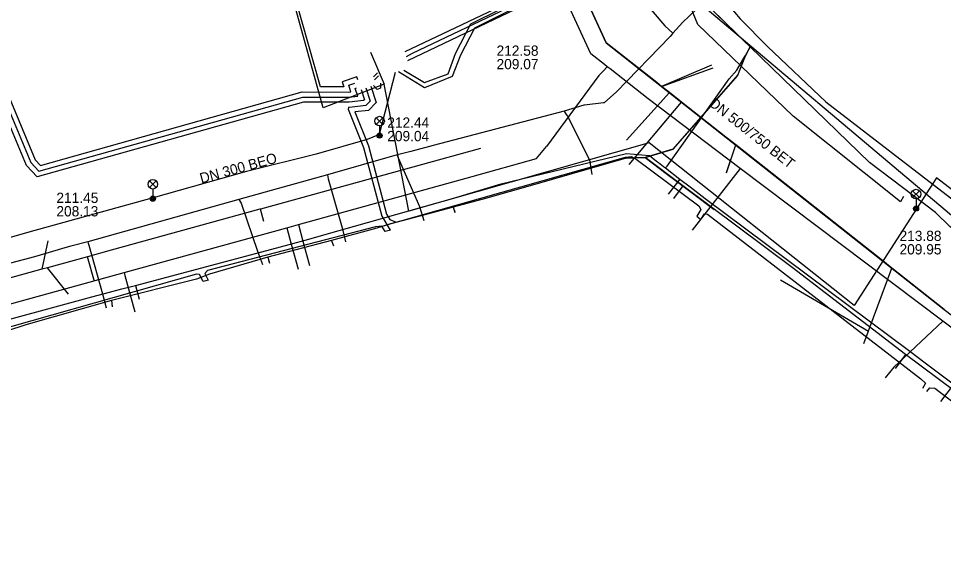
# Model space of a CAD drawing. Extents: x -595540 to -593988, y -1160850 to -1159202.
# Drawn here: x -595315.7 to -595243.6, y -1160720.8 to -1160678.3 of the extents above; entities that cross this region are included whole.
import ezdxf

# ---------------------------------------------------------------- set-up
doc = ezdxf.new("R2010")
doc.units = 0
for name, color, linetype in [('BKOM-ODVODNENI_trasa sítě', 7, 'Continuous'), ('BVK-JEDNOTNA_popisy', 7, 'Continuous'), ('BVK-JEDNOTNA_trasa sítě', 7, 'Continuous'), ('BVK-VODOVOD_trasa sítě', 7, 'Continuous'), ('CETIN_kabel podzemní', 7, 'Continuous'), ('DESTOVA_trasa neprovozované sítě', 7, 'Continuous'), ('DSP-SDEL-VODAFONE_kabel', 7, 'Continuous'), ('EON-NN_kabel', 7, 'Continuous'), ('EON-VN_kabel', 7, 'Continuous'), ('INNOGY-STL_trasa sítě', 7, 'Continuous'), ('JEDNOTNA_trasa neprovozované sítě', 7, 'Continuous'), ('TSB_kabel VO', 7, 'Continuous'), ('TSB_lampy VO', 7, 'Continuous')]:
    doc.layers.add(name, color=color, linetype=linetype)

msp = doc.modelspace()

# ---------------------------------------------------------------- linework, layer by layer
at = {"layer": 'BKOM-ODVODNENI_trasa sítě'}
for points in [[(-595328.652, -1160545.194), (-595323.701, -1160557.168), (-595307.991, -1160595.166), (-595289.318, -1160637.909), (-595269.901, -1160680.144), (-595243.565, -1160700.938), (-595203.101, -1160731.684), (-595169.808, -1160756.776), (-595134.211, -1160783.069), (-595091.899, -1160806.063), (-595046.729, -1160830.268), (-595023.064, -1160843.241)], [(-595265.59, -1160683.55), (-595261.58, -1160682.11)], [(-595260.54, -1160690.29), (-595259.81, -1160688.11)]]:
    msp.add_lwpolyline(points, dxfattribs=at)
at = {"layer": 'BVK-JEDNOTNA_popisy'}
for p, q in [((-595278.452, -1160681.286), (-595278.452, -1160681.286)), ((-595286.971, -1160686.897), (-595286.971, -1160686.897)), ((-595312.758, -1160692.759), (-595312.758, -1160692.759)), ((-595247.042, -1160695.724), (-595247.042, -1160695.724))]:
    msp.add_line(p, q, dxfattribs=at)
at = {"layer": 'BVK-JEDNOTNA_trasa sítě'}
for p, q in [((-595268.105, -1160689.634), (-595264.029, -1160684.78)), ((-595249.814, -1160703.588), (-595247.635, -1160697.725))]:
    msp.add_line(p, q, dxfattribs=at)
for points in [[(-595269.901, -1160680.144), (-595278.855, -1160660.668), (-595278.922, -1160660.522), (-595280.268, -1160657.593), (-595286.141, -1160644.819), (-595286.45, -1160644.149), (-595286.515, -1160644.007), (-595287.577, -1160641.697), (-595287.87, -1160641.06), (-595289.318, -1160637.909)], [(-595243.565, -1160700.938), (-595247.635, -1160697.725), (-595248.353, -1160697.158), (-595259.809, -1160688.112), (-595260.588, -1160687.497), (-595264.029, -1160684.78), (-595264.98, -1160684.03), (-595265.591, -1160683.547), (-595265.784, -1160683.395), (-595265.965, -1160683.252), (-595269.901, -1160680.144)], [(-595279.697, -1160688.393), (-595296.861, -1160693.117), (-595296.889, -1160693.125), (-595308.489, -1160696.318)], [(-595308.489, -1160696.318), (-595310.325, -1160696.824), (-595310.326, -1160696.824), (-595313.449, -1160697.686), (-595313.883, -1160697.806), (-595324.121, -1160700.629), (-595331.996, -1160702.801), (-595342.35, -1160705.656), (-595342.88, -1160705.802), (-595343.439, -1160705.956), (-595343.44, -1160705.956), (-595347.44, -1160707.06)]]:
    msp.add_lwpolyline(points, dxfattribs=at)
at = {"layer": 'BVK-VODOVOD_trasa sítě'}
for p, q in [((-595269.832, -1160682.016), (-595270.047, -1160681.847)), ((-595269.832, -1160682.016), (-595270.151, -1160682.359)), ((-595269.605, -1160682.19), (-595269.832, -1160682.016)), ((-595259.461, -1160689.961), (-595263.206, -1160694.759))]:
    msp.add_line(p, q, dxfattribs=at)
for points in [[(-595270.047, -1160681.847), (-595271.11, -1160681.01), (-595280.618, -1160660.385), (-595281.776, -1160657.853), (-595284.97, -1160650.87), (-595287.782, -1160644.862), (-595292.67, -1160634.42), (-595299.283, -1160620.367), (-595300.34, -1160618.12), (-595307.84, -1160601.91), (-595311.31, -1160594.38), (-595311.85, -1160592.829), (-595311.96, -1160592.419)], [(-595270.151, -1160682.359), (-595270.152, -1160682.36), (-595270.469, -1160682.699), (-595274.55, -1160688.227)], [(-595242.73, -1160702.546), (-595243.663, -1160701.844), (-595259.461, -1160689.961), (-595266.63, -1160684.52), (-595269.605, -1160682.19)], [(-595368.93, -1160714.969), (-595359.217, -1160712.316), (-595339.395, -1160706.854), (-595329.676, -1160704.176), (-595320.015, -1160701.514), (-595307.484, -1160698.061), (-595294.807, -1160694.568), (-595293.899, -1160694.318), (-595280.351, -1160690.585), (-595275.325, -1160689.181), (-595274.55, -1160688.227)], [(-595294.807, -1160694.568), (-595294.455, -1160695.844), (-595293.914, -1160697.809)], [(-595293.899, -1160694.318), (-595293.538, -1160695.628), (-595293.018, -1160697.515)], [(-595307.484, -1160698.061), (-595307.42, -1160698.293), (-595306.64, -1160701.123)], [(-595243.663, -1160701.844), (-595247.482, -1160705.431), (-595248.152, -1160706.269)]]:
    msp.add_lwpolyline(points, dxfattribs=at)
at = {"layer": 'CETIN_kabel podzemní'}
for points in [[(-595261.73, -1160677.5), (-595260.18, -1160679.01)], [(-595260.18, -1160679.01), (-595259.74, -1160679.44)], [(-595259.74, -1160679.44), (-595258.68, -1160680.47)], [(-595259.06, -1160681.17), (-595259.66, -1160682.69), (-595264.7, -1160688.44), (-595266.86, -1160689.09)], [(-595259.71, -1160682.29), (-595259.06, -1160681.17)], [(-595258.68, -1160680.47), (-595259.06, -1160681.17)], [(-595244.25, -1160693.37), (-595249.39, -1160689.48), (-595258.68, -1160680.47)], [(-595265.27, -1160689.91), (-595265.15, -1160689.76), (-595260.32, -1160682.95), (-595259.71, -1160682.29)], [(-595224.29, -1160682.2), (-595236.96, -1160698.92), (-595237.48, -1160698.78), (-595243.09, -1160694.5), (-595244.25, -1160693.37)], [(-595306.6, -1160699.07), (-595295.97, -1160696.24), (-595294.62, -1160695.88), (-595293.07, -1160695.45), (-595291.73, -1160695.07), (-595283.07, -1160692.63), (-595281.63, -1160692.22), (-595278.09, -1160691.14), (-595268.33, -1160688.77)], [(-595266.86, -1160689.09), (-595268.34, -1160689.15), (-595275.47, -1160691.19), (-595279.31, -1160692.28), (-595281.84, -1160692.97)], [(-595268.33, -1160688.77), (-595266.54, -1160688.94)], [(-595266.86, -1160689.09), (-595265.12, -1160690.41)], [(-595266.54, -1160688.94), (-595265.99, -1160689.37)], [(-595265.99, -1160689.37), (-595265.83, -1160689.49)], [(-595265.83, -1160689.49), (-595265.43, -1160689.79)], [(-595265.43, -1160689.79), (-595265.27, -1160689.91)], [(-595265.27, -1160689.91), (-595264.16, -1160690.77)], [(-595265.12, -1160690.41), (-595263.92, -1160691.31)], [(-595264.16, -1160690.77), (-595265.08, -1160691.96)], [(-595264.16, -1160690.77), (-595263.37, -1160691.38), (-595262.18, -1160692.29), (-595246.25, -1160704.2), (-595245.05, -1160705.1), (-595238.81, -1160709.77)], [(-595263.92, -1160691.31), (-595264.66, -1160692.28)], [(-595246.57, -1160704.46), (-595255.42, -1160697.66), (-595263.92, -1160691.31)], [(-595281.84, -1160692.97), (-595283.65, -1160693.46)], [(-595281.84, -1160692.97), (-595281.69, -1160693.38)], [(-595283.65, -1160693.46), (-595286.7, -1160694.27), (-595287.78, -1160694.59), (-595291.31, -1160695.57)], [(-595291.31, -1160695.57), (-595296.27, -1160696.87)], [(-595291.31, -1160695.57), (-595291.16, -1160695.97)], [(-595296.27, -1160696.87), (-595300.82, -1160698.19), (-595301.85, -1160698.58), (-595308.46, -1160700.25), (-595308.41, -1160700.71)], [(-595296.27, -1160696.87), (-595296.16, -1160697.34)], [(-595309.99, -1160699.96), (-595309.02, -1160699.69), (-595307.67, -1160699.34), (-595306.6, -1160699.07)], [(-595306.6, -1160699.07), (-595306.31, -1160700.13)], [(-595349.85, -1160710.99), (-595348.5, -1160710.61), (-595344.65, -1160709.53), (-595340.03, -1160708.24), (-595338.78, -1160707.89), (-595330.42, -1160705.55), (-595328.88, -1160705.12), (-595323.02, -1160703.54), (-595320.81, -1160702.88), (-595319.27, -1160702.47), (-595309.99, -1160699.96)], [(-595308.46, -1160700.25), (-595315.15, -1160702.14), (-595318.11, -1160703.09), (-595318.66, -1160703.25), (-595320.68, -1160703.83)], [(-595246.57, -1160704.46), (-595247.36, -1160705.52)], [(-595231.46, -1160715.95), (-595238.74, -1160710.31), (-595246.57, -1160704.46)]]:
    msp.add_lwpolyline(points, dxfattribs=at)
at = {"layer": 'DESTOVA_trasa neprovozované sítě'}
for p, q in [((-595261.686, -1160681.887), (-595265.591, -1160683.547)), ((-595268.313, -1160687.746), (-595264.98, -1160684.03)), ((-595260.533, -1160690.252), (-595259.809, -1160688.112)), ((-595313.43, -1160695.59), (-595313.883, -1160697.806)), ((-595311.82, -1160699.75), (-595313.449, -1160697.686)), ((-595249.466, -1160702.651), (-595256.33, -1160698.65))]:
    msp.add_line(p, q, dxfattribs=at)
at = {"layer": 'DSP-SDEL-VODAFONE_kabel'}
for p, q in [((-595264.696, -1160688.441), (-595259.656, -1160682.685)), ((-595266.861, -1160689.091), (-595261.485, -1160693.156)), ((-595281.841, -1160692.967), (-595281.713, -1160693.322)), ((-595286.705, -1160694.274), (-595287.78, -1160694.589)), ((-595291.306, -1160695.568), (-595291.176, -1160695.922)), ((-595296.268, -1160696.872), (-595296.164, -1160697.296)), ((-595300.824, -1160698.187), (-595301.845, -1160698.576)), ((-595308.462, -1160700.248), (-595308.407, -1160700.732)), ((-595246.569, -1160704.458), (-595247.386, -1160705.544))]:
    msp.add_line(p, q, dxfattribs=at)
for points in [[(-595221.485, -1160723.561), (-595229.603, -1160717.384), (-595238.742, -1160710.309), (-595246.569, -1160704.458), (-595255.422, -1160697.66), (-595263.924, -1160691.311), (-595266.861, -1160689.091), (-595264.696, -1160688.441), (-595259.656, -1160682.685), (-595259.057, -1160681.172), (-595258.679, -1160680.465), (-595261.734, -1160677.498), (-595265.204, -1160672.997), (-595267.895, -1160669.078), (-595270.969, -1160663.406), (-595276.178, -1160651.931), (-595281.186, -1160641.581), (-595282.771, -1160638.348), (-595287.635, -1160627.419)], [(-595259.656, -1160682.685), (-595259.057, -1160681.172), (-595258.679, -1160680.465), (-595261.734, -1160677.498), (-595265.204, -1160672.997)], [(-595268.337, -1160689.154), (-595266.861, -1160689.091), (-595264.696, -1160688.441)], [(-595268.337, -1160689.154), (-595275.47, -1160691.188), (-595279.311, -1160692.28), (-595281.841, -1160692.967), (-595286.705, -1160694.274)], [(-595213.279, -1160729.767), (-595221.485, -1160723.561), (-595229.603, -1160717.384), (-595238.742, -1160710.309), (-595246.569, -1160704.458), (-595255.422, -1160697.66), (-595263.924, -1160691.311), (-595264.655, -1160692.277)], [(-595287.78, -1160694.589), (-595291.306, -1160695.568), (-595296.268, -1160696.872), (-595300.824, -1160698.187)], [(-595301.845, -1160698.576), (-595308.462, -1160700.248), (-595315.147, -1160702.141), (-595318.106, -1160703.091)]]:
    msp.add_lwpolyline(points, dxfattribs=at)
at = {"layer": 'EON-NN_kabel'}
for points in [[(-595286.616, -1160628.762), (-595282.369, -1160638.18), (-595282.16, -1160638.63), (-595277.863, -1160647.491), (-595275.639, -1160652.13), (-595272.733, -1160658.667), (-595272.458, -1160659.226), (-595270.309, -1160663.798), (-595267.425, -1160668.365), (-595267.279, -1160670.212), (-595268.67, -1160671.132), (-595269.681, -1160671.836), (-595275.677, -1160676.126), (-595285.589, -1160680.85)], [(-595285.478, -1160681.219), (-595285.006, -1160680.965), (-595275.487, -1160676.421), (-595269.108, -1160671.839), (-595266.962, -1160670.365), (-595267.121, -1160668.185), (-595270.038, -1160663.633), (-595272.167, -1160659.02), (-595271.759, -1160658.524), (-595271.807, -1160658.456), (-595272.416, -1160658.529), (-595275.324, -1160651.96), (-595277.58, -1160647.271), (-595281.913, -1160638.35), (-595281.257, -1160637.946), (-595281.371, -1160637.893), (-595282.042, -1160638.018), (-595286.314, -1160628.606)], [(-595265.195, -1160671.498), (-595259.46, -1160678.281), (-595257.338, -1160680.433), (-595252.784, -1160684.757), (-595242.726, -1160692.497), (-595242.252, -1160692.666), (-595241.965, -1160692.491), (-595236.873, -1160685.671), (-595228.209, -1160674.512), (-595226.032, -1160671.135), (-595225.247, -1160668.904), (-595225.291, -1160667.517), (-595225.718, -1160665.302), (-595225.844, -1160664.768), (-595225.703, -1160664.421), (-595218.63, -1160657.428), (-595218.399, -1160657.198), (-595217.497, -1160656.307)], [(-595289.263, -1160683.03), (-595289.332, -1160682.816), (-595290.472, -1160683.187), (-595290.342, -1160683.587), (-595292.165, -1160683.582), (-595295.464, -1160671.927), (-595296.327, -1160667.878), (-595296.587, -1160667.418), (-595296.967, -1160667.058), (-595297.51, -1160666.795), (-595299.28, -1160666.972), (-595299.915, -1160667.102)], [(-595265.195, -1160671.498), (-595265.353, -1160671.311), (-595266.534, -1160670.514), (-595267.807, -1160671.296), (-595268.9, -1160672.125), (-595275.316, -1160676.723), (-595285.379, -1160681.549)], [(-595317.555, -1160681.758), (-595314.413, -1160689.265), (-595314.006, -1160689.704), (-595293.605, -1160683.978), (-595289.987, -1160683.988), (-595289.798, -1160683.966), (-595289.968, -1160683.443), (-595289.486, -1160683.286)], [(-595289.015, -1160683.791), (-595288.754, -1160684.594), (-595288.818, -1160684.659), (-595289.943, -1160684.788), (-595293.495, -1160684.778), (-595314.26, -1160690.606), (-595315.097, -1160689.705), (-595318.227, -1160682.226)], [(-595317.891, -1160681.992), (-595314.755, -1160689.485), (-595314.133, -1160690.155), (-595293.55, -1160684.378), (-595289.965, -1160684.388), (-595289.267, -1160684.308), (-595289.464, -1160683.7), (-595289.362, -1160683.667)], [(-595288.039, -1160682.8), (-595287.721, -1160682.481)], [(-595287.485, -1160683.287), (-595287.488, -1160683.678), (-595287.753, -1160683.793), (-595288.054, -1160683.478)], [(-595287.962, -1160683.033), (-595287.659, -1160682.714)], [(-595288.633, -1160683.672), (-595288.299, -1160684.699), (-595288.631, -1160685.04), (-595289.921, -1160685.188), (-595289.98, -1160685.188), (-595290.022, -1160685.319), (-595288.811, -1160688.313), (-595287.398, -1160693.669), (-595286.753, -1160694.757), (-595286.826, -1160694.781), (-595287.132, -1160694.866), (-595287.397, -1160694.434), (-595287.888, -1160694.502), (-595300.984, -1160697.912), (-595301.179, -1160698.143), (-595300.929, -1160698.647), (-595301.116, -1160698.702), (-595301.309, -1160698.755), (-595301.604, -1160698.217), (-595301.841, -1160698.181), (-595321.127, -1160703.635)], [(-595288.254, -1160683.543), (-595287.844, -1160684.805), (-595288.444, -1160685.421), (-595289.496, -1160685.542), (-595288.431, -1160688.187), (-595287.026, -1160693.511), (-595286.768, -1160693.934), (-595286.279, -1160694.136), (-595268.396, -1160689.077), (-595267.944, -1160689.012), (-595267.56, -1160689.215), (-595262.68, -1160692.867), (-595262.521, -1160693.146), (-595262.838, -1160693.673), (-595262.683, -1160693.797), (-595262.526, -1160693.916), (-595262.254, -1160693.486), (-595262.001, -1160693.499), (-595245.379, -1160706.341), (-595245.024, -1160706.695), (-595245.246, -1160707.099)], [(-595244.92, -1160707.348), (-595244.691, -1160707.051), (-595244.289, -1160707.066), (-595230.718, -1160717.43), (-595230.624, -1160717.537), (-595230.95, -1160718.048), (-595230.789, -1160718.168), (-595230.63, -1160718.289), (-595230.364, -1160717.873), (-595230.088, -1160717.892), (-595219.776, -1160725.732), (-595219.24, -1160725.99), (-595218.77, -1160726.36)]]:
    msp.add_lwpolyline(points, dxfattribs=at)
at = {"layer": 'EON-VN_kabel'}
for points in [[(-595285.683, -1160682.281), (-595284.067, -1160683.257), (-595282.218, -1160682.563), (-595281.646, -1160680.972), (-595280.448, -1160678.67), (-595275.785, -1160676.342), (-595274.79, -1160675.768), (-595269.17, -1160671.731), (-595267.619, -1160670.326), (-595267.458, -1160669.066), (-595270.234, -1160664.473), (-595271.19, -1160661.561), (-595275.869, -1160652.267), (-595276.686, -1160650.483), (-595277.916, -1160647.435), (-595282.362, -1160638.142), (-595286.833, -1160628.81)], [(-595286.439, -1160628.641), (-595277.524, -1160647.305), (-595276.331, -1160650.314), (-595275.297, -1160652.078), (-595270.842, -1160661.386), (-595269.855, -1160664.323), (-595267.042, -1160668.961), (-595267.389, -1160670.762), (-595268.915, -1160672.046), (-595275.593, -1160676.696), (-595280.181, -1160678.999), (-595281.261, -1160681.109), (-595281.901, -1160682.787), (-595284.074, -1160683.662), (-595286.081, -1160682.406)]]:
    msp.add_lwpolyline(points, dxfattribs=at)
at = {"layer": 'INNOGY-STL_trasa sítě'}
for points in [[(-595292.74, -1160626.09), (-595286.32, -1160639.96), (-595285.21, -1160642.46), (-595285.054, -1160642.794), (-595284.87, -1160643.19), (-595284.179, -1160644.763), (-595283.75, -1160645.74), (-595281.27, -1160650.84), (-595277.81, -1160657.87), (-595277.05, -1160659.51), (-595276.31, -1160661.16), (-595275.32, -1160663.46), (-595275.07, -1160664.01), (-595274.73, -1160664.77), (-595272.62, -1160668.93), (-595270.69, -1160672.22), (-595269.21, -1160674.24), (-595267.16, -1160676.66), (-595265.34, -1160678.82), (-595264.7, -1160679.39), (-595263.92, -1160678.54), (-595262.46, -1160677.15), (-595262.2, -1160677.41), (-595239.02, -1160696.95)], [(-595264.7, -1160679.39), (-595264.93, -1160679.65), (-595269.09, -1160683.97), (-595270.06, -1160684.83), (-595270.11, -1160684.836), (-595271.6, -1160685.014), (-595271.65, -1160685.02), (-595273.17, -1160685.469), (-595283.388, -1160688.163), (-595283.669, -1160688.236), (-595285.145, -1160688.618), (-595285.855, -1160688.801), (-595286.206, -1160688.888), (-595291.636, -1160690.444), (-595298.533, -1160692.36), (-595310.309, -1160695.665), (-595311.642, -1160696), (-595311.925, -1160696.085), (-595314.467, -1160696.848), (-595319.004, -1160698.038)], [(-595273.17, -1160685.469), (-595273.024, -1160685.749), (-595272.927, -1160685.88), (-595271.212, -1160689.287), (-595271.031, -1160690.427)], [(-595286.206, -1160688.888), (-595286.11, -1160689.114), (-595284.451, -1160692.906), (-595284.112, -1160694)], [(-595291.636, -1160690.444), (-595291.57, -1160690.749), (-595290.48, -1160694.578), (-595290.221, -1160695.662)], [(-595298.533, -1160692.36), (-595298.362, -1160692.656), (-595297.092, -1160696.398), (-595296.703, -1160697.432)], [(-595310.309, -1160695.665), (-595310.28, -1160695.766), (-595310.256, -1160695.851), (-595310.238, -1160695.915), (-595309.157, -1160699.711), (-595308.878, -1160700.821)], [(-595238.762, -1160701.465), (-595238.85, -1160701.574), (-595238.87, -1160701.6), (-595238.95, -1160701.7), (-595241.94, -1160705.61), (-595243.859, -1160708.12)]]:
    msp.add_lwpolyline(points, dxfattribs=at)
at = {"layer": 'JEDNOTNA_trasa neprovozované sítě'}
for p, q in [((-595296.596, -1160694.082), (-595296.861, -1160693.117)), ((-595309.794, -1160698.752), (-595310.326, -1160696.824))]:
    msp.add_line(p, q, dxfattribs=at)
at = {"layer": 'TSB_kabel VO'}
for points in [[(-595287.21, -1160683.37), (-595291.96, -1160685.22), (-595297.34, -1160665.79), (-595293.69, -1160664.92), (-595285.21, -1160662.02), (-595274.23, -1160657.83), (-595270.1, -1160665.79), (-595264.496, -1160674.146), (-595264.68, -1160674.575), (-595266.639, -1160675.126), (-595264.496, -1160674.146), (-595269.9, -1160665.67), (-595274.3, -1160657.55), (-595279.93, -1160645.054), (-595281.829, -1160645.299), (-595280.052, -1160644.564), (-595282.86, -1160638.54), (-595291.23, -1160620.82), (-595293.55, -1160616.115), (-595293.86, -1160616.11), (-595295.06, -1160616.52), (-595295.09, -1160616.76)], [(-595246.724, -1160692.138), (-595246.958, -1160692.557), (-595255.326, -1160685.862), (-595262.76, -1160678.724), (-595264.501, -1160674.468), (-595266.627, -1160675.177)], [(-595288.28, -1160680.87), (-595287.21, -1160683.37)], [(-595286.365, -1160682.476), (-595287.574, -1160687.198), (-595287.57, -1160687.38), (-595287.656, -1160687.321), (-595288.53, -1160687.69), (-595292.52, -1160688.84), (-595297.95, -1160690.18), (-595305.211, -1160692.224), (-595305.24, -1160692.3), (-595305.329, -1160692.256), (-595314.9, -1160694.91), (-595325.86, -1160698.053)], [(-595241.137, -1160689.85), (-595240.14, -1160690.42), (-595241.91, -1160692.42), (-595244.162, -1160690.682), (-595250.58, -1160700.63), (-595266.56, -1160687.94), (-595285.28, -1160693.28), (-595287.21, -1160683.37)]]:
    msp.add_lwpolyline(points, dxfattribs=at)
at = {"layer": 'TSB_lampy VO'}
for p, q in [((-595287.835, -1160686.52), (-595287.305, -1160685.99)), ((-595287.835, -1160685.99), (-595287.305, -1160686.52)), ((-595287.835, -1160686.52), (-595287.305, -1160685.99)), ((-595287.835, -1160685.99), (-595287.305, -1160686.52)), ((-595287.57, -1160686.63), (-595287.57, -1160687.38)), ((-595287.57, -1160686.63), (-595287.57, -1160687.38)), ((-595305.505, -1160691.44), (-595304.975, -1160690.91)), ((-595305.505, -1160690.91), (-595304.975, -1160691.44)), ((-595305.505, -1160691.44), (-595304.975, -1160690.91)), ((-595305.505, -1160690.91), (-595304.975, -1160691.44)), ((-595305.24, -1160691.55), (-595305.24, -1160692.3)), ((-595305.24, -1160691.55), (-595305.24, -1160692.3)), ((-595246.02, -1160692.211), (-595245.49, -1160691.681)), ((-595246.02, -1160691.681), (-595245.49, -1160692.211)), ((-595246.02, -1160692.211), (-595245.49, -1160691.681)), ((-595246.02, -1160691.681), (-595245.49, -1160692.211)), ((-595245.755, -1160692.321), (-595245.755, -1160693.071)), ((-595245.755, -1160692.321), (-595245.755, -1160693.071))]:
    msp.add_line(p, q, dxfattribs=at)
for centre, radius in [((-595287.57, -1160686.255), 0.375), ((-595287.57, -1160686.255), 0.375), ((-595287.57, -1160687.38), 0.2), ((-595287.57, -1160687.38), 0.2), ((-595287.57, -1160687.38), 0.145), ((-595287.57, -1160687.38), 0.145), ((-595287.57, -1160687.38), 0.0876), ((-595287.57, -1160687.38), 0.0876), ((-595305.24, -1160691.175), 0.375), ((-595305.24, -1160691.175), 0.375), ((-595245.755, -1160691.946), 0.375), ((-595245.755, -1160691.946), 0.375), ((-595305.24, -1160692.3), 0.2), ((-595305.24, -1160692.3), 0.2), ((-595305.24, -1160692.3), 0.145), ((-595305.24, -1160692.3), 0.145), ((-595305.24, -1160692.3), 0.0876), ((-595305.24, -1160692.3), 0.0876), ((-595245.755, -1160693.071), 0.2), ((-595245.755, -1160693.071), 0.2), ((-595245.755, -1160693.071), 0.145), ((-595245.755, -1160693.071), 0.145), ((-595245.755, -1160693.071), 0.0876), ((-595245.755, -1160693.071), 0.0876)]:
    msp.add_circle(centre, radius, dxfattribs=at)

# ---------------------------------------------------------------- texts
at = {"layer": 'BVK-JEDNOTNA_popisy'}
for s, p in [('212.58', (-595278.452, -1160681.161)), ('209.07', (-595278.452, -1160682.211)), ('212.44', (-595286.971, -1160686.772)), ('209.04', (-595286.971, -1160687.822)), ('211.45', (-595312.758, -1160692.634)), ('208.13', (-595312.758, -1160693.684)), ('213.88', (-595247.042, -1160695.599)), ('209.95', (-595247.042, -1160696.649))]:
    msp.add_text(s, height=0.8, dxfattribs=at).set_placement(p)
for s, rotation, p in [('DN 500/750 BET', 321.7158, (-595261.95, -1160684.995)), ('DN 300 BEO', 15.41256, (-595301.458, -1160691.122))]:
    msp.add_text(s, height=0.8, rotation=rotation, dxfattribs=at).set_placement(p)

doc.saveas('drawing.dxf')
